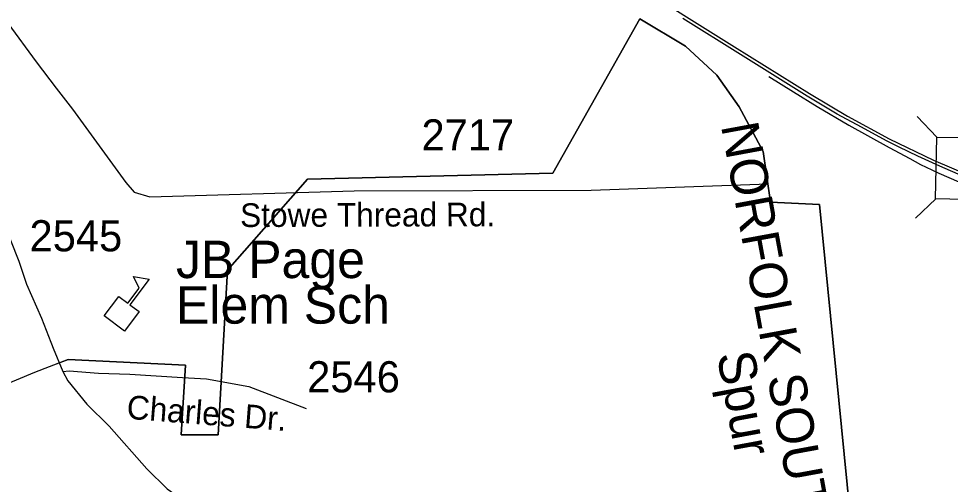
# Model space of a CAD drawing. Extents: x 1364363 to 1407445, y 538563 to 573342.
# Drawn here: x 1392969 to 1396708, y 545834 to 547703 of the extents above; entities that cross this region are included whole.
import ezdxf

# ---------------------------------------------------------------- set-up
doc = ezdxf.new("R2010")
doc.units = 0
for name, color, linetype in [('Default', 7, 'Continuous'), ('Exist Boundary Political City Limit New Hole', 7, 'Continuous'), ('Exist Cultural Educational Facility Elementary CELL', 7, 'Continuous'), ('Exist Cultural Educational Facility Elementary Label', 7, 'Continuous'), ('Exist Railroad Mainline', 7, 'Continuous'), ('Exist Railroad Mainline Label', 7, 'Continuous'), ('Exist Railroad Siding', 7, 'Continuous'), ('Exist Railroad Spur', 7, 'Continuous'), ('Exist Road Secondary Type 51 Attributed', 7, 'Continuous'), ('Exist Road Secondary Type 51 Label', 7, 'Continuous'), ('Exist Road Secondary Type 51 Number Label', 7, 'Continuous')]:
    doc.layers.add(name, color=color, linetype=linetype)

msp = doc.modelspace()

# ---------------------------------------------------------------- linework, layer by layer
at = {"layer": 'Default'}
for p, q in [((1396575.3, 547309.6), (1396653.5, 547227.8)), ((1396575.3, 547309.6), (1396653.5, 547227.8)), ((1396650.2, 546980), (1396568.4, 546901.7)), ((1396650.2, 546980), (1396568.4, 546901.7))]:
    msp.add_line(p, q, dxfattribs=at)
msp.add_lwpolyline([(1396769.3, 547225.3), (1396763.9, 546977.5), (1396648.1, 546980), (1396653.5, 547227.8)], close=True, dxfattribs=at)
msp.add_lwpolyline([(1396769.3, 547225.3), (1396763.9, 546977.5), (1396648.1, 546980), (1396653.5, 547227.8)], close=True, dxfattribs=at)
at = {"layer": 'Exist Boundary Political City Limit New Hole'}
for points in [[(1392939.9, 542316.6), (1393175.9, 542530.1), (1393445, 542792.4), (1393703.2, 543050.7), (1393879.4, 543176.6), (1394061.4, 543257.9), (1394513.4, 543558.9), (1394805, 543710.6), (1395120.5, 543882.9), (1394827.5, 544687.8), (1396348.4, 545345.4), (1396305.6, 545725.9), (1396183.1, 546956.9), (1395987.2, 546966.9), (1395957.4, 547169.6), (1395861, 547349.1), (1395771.4, 547475.4), (1395645.2, 547591.8), (1395462.6, 547701.4), (1395113.6, 547082.1), (1394128.9, 547058.8), (1393807.5, 546693.6)], [(1393807.5, 546693.6), (1394128.9, 547058.8), (1395113.6, 547082.1), (1395462.6, 547701.4), (1395645.2, 547591.8), (1395771.4, 547475.4), (1395861, 547349.1), (1395957.4, 547169.6), (1395987.2, 546966.9), (1396183.1, 546956.9), (1396305.6, 545725.9), (1396348.4, 545345.4), (1394827.5, 544687.8), (1395120.5, 543882.9), (1394805, 543710.6), (1394513.4, 543558.9), (1394061.4, 543257.9), (1393879.4, 543176.6), (1393703.2, 543050.7), (1393445, 542792.4), (1393175.9, 542530.1), (1393099.7, 542461.1)], [(1393807.5, 546693.6), (1393770.5, 546032.5), (1393622.1, 546032.5), (1393639.4, 546312.5), (1393167.5, 546335.8), (1393033.4, 546283.3), (1392264.2, 545962.6)], [(1393099.7, 546309.3), (1393167.5, 546335.8), (1393639.4, 546312.5), (1393622.1, 546032.5), (1393770.5, 546032.5), (1393807.5, 546693.6)]]:
    msp.add_lwpolyline(points, dxfattribs=at)
at = {"layer": 'Exist Cultural Educational Facility Elementary CELL'}
msp.add_lwpolyline([(1393312.3, 546510.2), (1393371.1, 546588.6), (1393407.9, 546560.9), (1393452.9, 546621), (1393429.8, 546668.6), (1393492.7, 546658), (1393415.6, 546555.2), (1393452.4, 546527.6), (1393393.6, 546449.2)], close=True, dxfattribs=at)
msp.add_lwpolyline([(1393312.3, 546510.2), (1393371.1, 546588.6), (1393407.9, 546560.9), (1393452.9, 546621), (1393429.8, 546668.6), (1393492.7, 546658), (1393415.6, 546555.2), (1393452.4, 546527.6), (1393393.6, 546449.2)], close=True, dxfattribs=at)
at = {"layer": 'Exist Railroad Mainline'}
msp.add_lwpolyline([(1396761.6, 547069.7), (1396666, 547110.7), (1396577.8, 547150.6), (1396502.6, 547186.4), (1396451.6, 547212), (1396351.3, 547266.7), (1396254.6, 547318.8), (1396134.3, 547391.8), (1395866.4, 547558.8), (1395635.2, 547703.8)], dxfattribs=at)
msp.add_lwpolyline([(1396761.6, 547069.7), (1396666, 547110.7), (1396577.8, 547150.6), (1396502.6, 547186.4), (1396451.6, 547212), (1396351.3, 547266.7), (1396254.6, 547318.8), (1396134.3, 547391.8), (1395866.4, 547558.8), (1395635.2, 547703.8)], dxfattribs=at)
at = {"layer": 'Exist Railroad Siding'}
msp.add_lwpolyline([(1394096.7, 548682.9), (1394889.3, 548186.3), (1395000, 548117.4), (1395842.2, 547589.8), (1396142.7, 547401.8), (1396225.8, 547352.4), (1396296.1, 547311.9), (1396462.7, 547221), (1396641.4, 547134.9), (1396784.8, 547073.4)], dxfattribs=at)
msp.add_lwpolyline([(1394096.7, 548682.9), (1394889.3, 548186.3), (1395000, 548117.4), (1395842.2, 547589.8), (1396142.7, 547401.8), (1396225.8, 547352.4), (1396296.1, 547311.9), (1396462.7, 547221), (1396641.4, 547134.9), (1396784.8, 547073.4)], dxfattribs=at)
at = {"layer": 'Exist Railroad Spur'}
msp.add_lwpolyline([(1395979.6, 547470.7), (1396079.3, 547408.5), (1396174.1, 547349.9), (1396300.4, 547275), (1396462.6, 547185.5), (1396545.3, 547141.3), (1396589.1, 547117.9), (1396634.6, 547096), (1396661.7, 547083.4), (1396742.7, 547048.2)], dxfattribs=at)
msp.add_lwpolyline([(1395979.6, 547470.7), (1396079.3, 547408.5), (1396174.1, 547349.9), (1396300.4, 547275), (1396462.6, 547185.5), (1396545.3, 547141.3), (1396589.1, 547117.9), (1396634.6, 547096), (1396661.7, 547083.4), (1396742.7, 547048.2)], dxfattribs=at)
at = {"layer": 'Exist Road Secondary Type 51 Attributed'}
for points in [[(1392926.1, 547684.8), (1393040, 547528.9), (1393119.8, 547424.2), (1393185.2, 547339.7), (1393399.6, 547045.8), (1393433.1, 547006.7), (1393496.2, 546987.3), (1394315.3, 547012.3), (1395266.4, 547015.2), (1395978.9, 547040.2)], [(1393099.7, 547450.6), (1393119.8, 547424.2), (1393185.2, 547339.7), (1393399.6, 547045.8), (1393433.1, 547006.7), (1393496.2, 546987.3), (1394315.3, 547012.3), (1395266.4, 547015.2), (1395978.9, 547040.2)], [(1392377.5, 547184.9), (1392430.3, 547162.2), (1392502.3, 547141.7), (1392675.7, 547084.5), (1392724, 547066.2), (1392752.8, 547047.9), (1392810.5, 547004.9), (1392844.3, 546971.5), (1392883.1, 546914.5), (1392908.6, 546872.6), (1392937.1, 546813.9), (1392970.5, 546729.8), (1393000.7, 546636.9), (1393061.2, 546501.7), (1393107.9, 546380.3), (1393147.2, 546287.1)], [(1393099.7, 546401.6), (1393107.9, 546380.3), (1393147.2, 546287.1)], [(1393147.2, 546287.1), (1393171.9, 546289.5), (1393290.1, 546280.5), (1393416.1, 546276), (1393626.7, 546262.9), (1393723.6, 546257.9), (1393893, 546226.3), (1394122.6, 546138.9)], [(1393147.2, 546287.1), (1393171.9, 546289.5), (1393290.1, 546280.5), (1393416.1, 546276), (1393626.7, 546262.9), (1393723.6, 546257.9), (1393893, 546226.3), (1394122.6, 546138.9)], [(1393147.2, 546287.1), (1393167.1, 546249.5), (1393243.3, 546155.8), (1393331.9, 546068.1), (1393484, 545896.7), (1393565.3, 545816.6), (1393628, 545772.6), (1393680, 545749.9), (1393744.4, 545729.7)], [(1393147.2, 546287.1), (1393167.1, 546249.5), (1393243.3, 546155.8), (1393331.9, 546068.1), (1393484, 545896.7), (1393565.3, 545816.6), (1393628, 545772.6), (1393680, 545749.9), (1393744.4, 545729.7)]]:
    msp.add_lwpolyline(points, dxfattribs=at)

# ---------------------------------------------------------------- texts
at = {"layer": 'Exist Cultural Educational Facility Elementary Label'}
for s, p in [('JB Page', (1393600.8, 546661.9)), ('JB Page', (1393600.8, 546661.9)), ('Elem Sch', (1393600.8, 546479.1)), ('Elem Sch', (1393600.8, 546479.1))]:
    msp.add_text(s, height=150, dxfattribs=at).set_placement(p)
at = {"layer": 'Exist Railroad Mainline Label'}
for s, p in [('NORFOLK SOUTHERN', (1395787.3, 547273.5)), ('NORFOLK SOUTHERN', (1395787.3, 547273.5)), (' Spur', (1395760.6, 546410)), (' Spur', (1395760.6, 546410))]:
    msp.add_text(s, height=150, rotation=280.4475, dxfattribs=at).set_placement(p)
at = {"layer": 'Exist Road Secondary Type 51 Label'}
for s, rotation, p in [('Stowe Thread Rd.', 0.175, (1393858, 546866.7)), ('Stowe Thread Rd.', 0.175, (1393858, 546866.7)), ('Charles Dr.', 355.5838, (1393400.4, 546097.9)), ('Charles Dr.', 355.5838, (1393400.4, 546097.9))]:
    msp.add_text(s, height=95, rotation=rotation, dxfattribs=at).set_placement(p)
at = {"layer": 'Exist Road Secondary Type 51 Number Label'}
for s, p in [('2717', (1394586.1, 547173.7)), ('2717', (1394586.1, 547173.7)), ('2545', (1393013, 546769.1)), ('2546', (1394127.3, 546203.4)), ('2546', (1394127.3, 546203.4))]:
    msp.add_text(s, height=125, dxfattribs=at).set_placement(p)

doc.saveas('drawing.dxf')
